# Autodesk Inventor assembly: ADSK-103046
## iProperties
Shininess: 20.0
Created: 2001-04
Part Number: ADSK-103046
Document SubType Name: Assembly
Designer: Administrator
Stock Number: ADSK-103046
Density: 0.0
Volumn: 0.0
Area: 0.0
PropertySet Name: Model Information
Control State: 0
Master: False
Checked Out: False
Author: Administrator
